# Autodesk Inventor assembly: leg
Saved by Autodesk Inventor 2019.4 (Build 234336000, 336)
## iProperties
Created: 2020-09
Part Number: leg
Document SubType Name: Assembly
Designer: Administrator
Title: leg
Author: Administrator
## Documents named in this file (5)
- c:\worker\convert-fusion-r07\tmp\job-1\164\output\files\c50c4620-2026-4653-9277-f8972be5ac5a\leg_1.iam
- c:\worker\convert-fusion-r07\tmp\job-1\164\output\files\c50c4620-2026-4653-9277-f8972be5ac5a\legA.ipt
- c:\worker\convert-fusion-r07\tmp\job-1\164\output\files\c50c4620-2026-4653-9277-f8972be5ac5a\legB.ipt
- c:\worker\convert-fusion-r07\tmp\job-1\164\output\files\c50c4620-2026-4653-9277-f8972be5ac5a\legC.ipt
- c:\worker\convert-fusion-r07\tmp\job-1\164\output\files\c50c4620-2026-4653-9277-f8972be5ac5a\legD.ipt
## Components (4 placed, 4 different names)
1. legA:1
2. legB:1
3. legC:1
4. legD:1
